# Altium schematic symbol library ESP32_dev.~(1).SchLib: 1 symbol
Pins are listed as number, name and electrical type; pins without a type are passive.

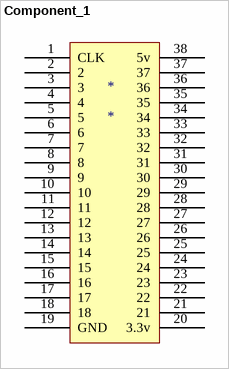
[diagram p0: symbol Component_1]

## Component_1
designator *
pins: 1 CLK "5v", 2, 3, 4, 5, 6, 7, 8, 9, 10, 11, 12, 13, 14, 15, 16, 17, 18, 19 GND, 20 3.3v, 21, 22, 23, 24, 25, 26, 27, 28, 29, 30, 31, 32, 33, 34, 35, 36, 37, 38 5v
